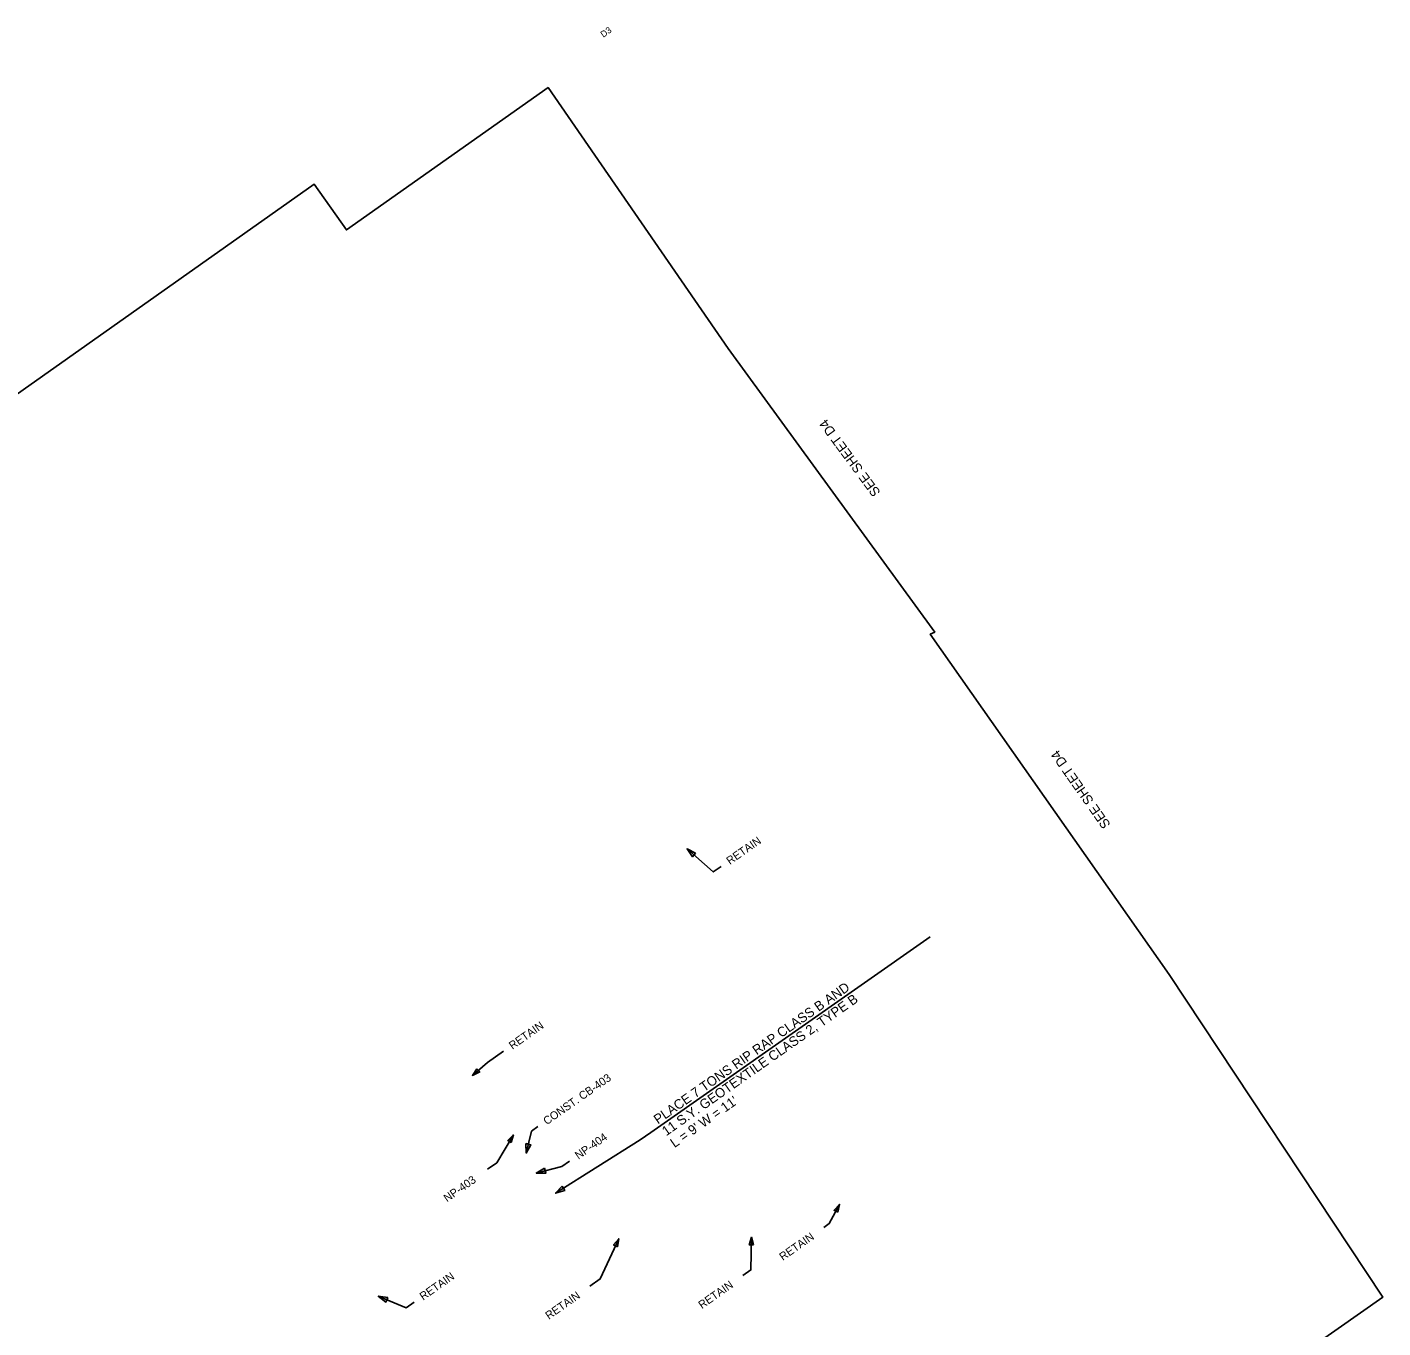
# Model space of a CAD drawing. Extents: x 1605049 to 1606865, y 1089598 to 1091250.
# Drawn here: x 1605969 to 1606816, y 1090437 to 1091250 of the extents above; entities that cross this region are included whole.
import ezdxf

# ---------------------------------------------------------------- set-up
doc = ezdxf.new("R2010")
doc.units = 0
for name, color, linetype in [('Plan_Clip', 7, 'Continuous'), ('RD_SHT_Bndy', 7, 'Continuous'), ('RD_SHT_MatchLine', 7, 'Continuous'), ('RD_TX_Drainage', 7, 'Continuous')]:
    doc.layers.add(name, color=color, linetype=linetype)

msp = doc.modelspace()

# ---------------------------------------------------------------- linework, layer by layer
at = {"layer": 'Plan_Clip'}
msp.add_lwpolyline([(1605233.56, 1090111.04), (1605405.83, 1089865.44), (1605593.12, 1089598.42), (1606815.94, 1090456.14), (1606682.28, 1090657.78), (1606533.03, 1090870.55), (1606535.89, 1090871.82), (1606406.67, 1091049.1), (1606294.17, 1091212.27), (1606168.16, 1091123.23), (1606148, 1091151.76), (1605049.41, 1090375.46)], close=True, dxfattribs=at)
msp.add_lwpolyline([(1605233.56, 1090111.04), (1605405.83, 1089865.44), (1605593.12, 1089598.42), (1606815.94, 1090456.14), (1606682.28, 1090657.78), (1606533.03, 1090870.55), (1606535.89, 1090871.82), (1606406.67, 1091049.1), (1606294.17, 1091212.27), (1606168.16, 1091123.23), (1606148, 1091151.76), (1605049.41, 1090375.46)], close=True, dxfattribs=at)
msp.add_lwpolyline([(1605233.56, 1090111.04), (1605405.83, 1089865.44), (1605593.12, 1089598.42), (1606815.94, 1090456.14), (1606682.28, 1090657.78), (1606533.03, 1090870.55), (1606535.89, 1090871.82), (1606406.67, 1091049.1), (1606294.17, 1091212.27), (1606168.16, 1091123.23), (1606148, 1091151.76), (1605049.41, 1090375.46)], close=True, dxfattribs=at)
msp.add_lwpolyline([(1605233.56, 1090111.04), (1605405.83, 1089865.44), (1605593.12, 1089598.42), (1606815.94, 1090456.14), (1606682.28, 1090657.78), (1606533.03, 1090870.55), (1606535.89, 1090871.82), (1606406.67, 1091049.1), (1606294.17, 1091212.27), (1606168.16, 1091123.23), (1606148, 1091151.76), (1605049.41, 1090375.46)], close=True, dxfattribs=at)
msp.add_lwpolyline([(1605233.56, 1090111.04), (1605405.83, 1089865.44), (1605593.12, 1089598.42), (1606815.94, 1090456.14), (1606682.28, 1090657.78), (1606533.03, 1090870.55), (1606535.89, 1090871.82), (1606406.67, 1091049.1), (1606294.17, 1091212.27), (1606168.16, 1091123.23), (1606148, 1091151.76), (1605049.41, 1090375.46)], close=True, dxfattribs=at)
at = {"layer": 'RD_TX_Drainage'}
msp.add_line((1606532.92, 1090681.47), (1606358.44, 1090559.09), dxfattribs=at)
for points in [[(1606402.29, 1090725.4), (1606397.4, 1090721.97), (1606381.05, 1090736.45)], [(1606266.38, 1090609.89), (1606256.41, 1090602.9), (1606246.94, 1090594.75)], [(1606287.84, 1090562.71), (1606283.81, 1090559.89), (1606280.53, 1090546.16)], [(1606256.42, 1090536.18), (1606262.07, 1090540.14), (1606272.55, 1090557.55)], [(1606358.44, 1090559.09), (1606351.75, 1090554.4), (1606298.93, 1090521.11)], [(1606307.64, 1090541.24), (1606302.83, 1090537.87), (1606286.81, 1090533.73)], [(1606466.45, 1090499.71), (1606469.89, 1090502.12), (1606476.36, 1090514.14)], [(1606415.87, 1090469.59), (1606421, 1090473.18), (1606421.29, 1090493.62)], [(1606320.22, 1090462.92), (1606326.82, 1090467.55), (1606338.36, 1090492.62)], [(1606210.56, 1090453.1), (1606205.51, 1090449.55), (1606188.03, 1090456.7)]]:
    msp.add_lwpolyline(points, dxfattribs=at)
for points in [[(1606386.42, 1090733.77), (1606381.05, 1090736.45), (1606384.36, 1090731.44)], [(1606249.76, 1090598.88), (1606246.94, 1090594.75), (1606251.44, 1090596.92)], [(1606271.17, 1090552.74), (1606272.55, 1090557.55), (1606268.95, 1090554.08)], [(1606280.36, 1090552.16), (1606280.53, 1090546.16), (1606283.39, 1090551.43)], [(1606292.03, 1090536.68), (1606286.81, 1090533.73), (1606292.81, 1090533.67)], [(1606303.01, 1090525.51), (1606298.93, 1090521.11), (1606304.66, 1090522.88)], [(1606475.21, 1090509.28), (1606476.36, 1090514.14), (1606472.93, 1090510.5)], [(1606422.52, 1090488.77), (1606421.29, 1090493.62), (1606419.93, 1090488.81)], [(1606337.51, 1090487.69), (1606338.36, 1090492.62), (1606335.16, 1090488.77)], [(1606193.98, 1090455.95), (1606188.03, 1090456.7), (1606192.81, 1090453.07)]]:
    msp.add_lwpolyline(points, close=True, dxfattribs=at)

# ---------------------------------------------------------------- texts
at = {"layer": 'RD_SHT_Bndy'}
msp.add_text('D3', height=4, rotation=35.04683, dxfattribs=at).set_placement((1606328.71, 1091243.32))
at = {"layer": 'RD_SHT_MatchLine'}
for rotation, p in [(126.48715, (1606502.24, 1090959.31)), (125.0981, (1606646.01, 1090751.63))]:
    msp.add_text('SEE SHEET D4', height=6, rotation=rotation, dxfattribs=at).set_placement(p)
at = {"layer": 'RD_TX_Drainage'}
for s, height, p in [('RETAIN', 5, (1606407.82, 1090726.23)), ('PLACE 7 TONS RIP RAP CLASS B AND', 6, (1606362.86, 1090564.02)), ('11 S.Y. GEOTEXTILE CLASS 2, TYPE B', 6, (1606368.03, 1090556.65)), ('RETAIN', 5, (1606271.91, 1090610.72)), ('CONST. CB-403', 5, (1606293.37, 1090563.54)), ("L = 9' W = 11'", 6, (1606373.2, 1090549.28)), ('NP-404', 5, (1606313.17, 1090542.06)), ('NP-403', 5, (1606231.07, 1090515.35)), ('RETAIN', 5, (1606440.91, 1090478.74)), ('RETAIN', 5, (1606216.09, 1090453.92)), ('RETAIN', 5, (1606294.68, 1090441.95)), ('RETAIN', 5, (1606390.33, 1090448.62))]:
    msp.add_text(s, height=height, rotation=35.04683, dxfattribs=at).set_placement(p)

doc.saveas('drawing.dxf')
